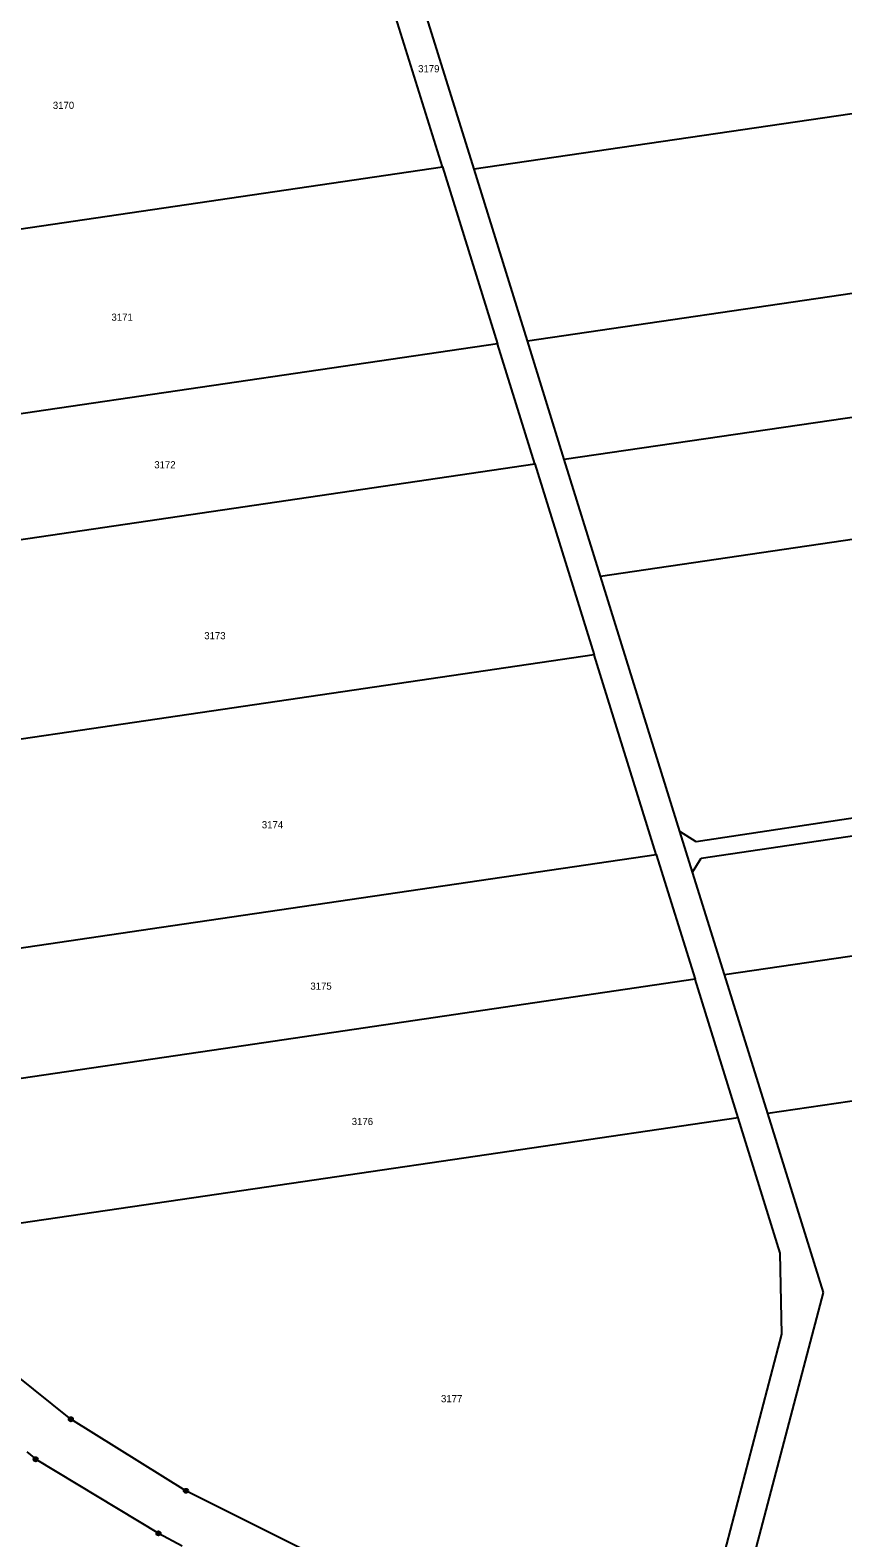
# Model space of a CAD drawing. Extents: x -618848 to -615803, y -1044450 to -1042254.
# Drawn here: x -616674.5 to -616481.6, y -1043703.1 to -1043345.1 of the extents above; entities that cross this region are included whole.
import ezdxf

# ---------------------------------------------------------------- set-up
doc = ezdxf.new("R2010")
doc.units = 0
doc.header["$LTSCALE"] = 0.68
doc.layers.add('1', color=7, linetype='Continuous', lineweight=25)
doc.layers.add('8', color=7, linetype='Continuous', lineweight=25)
doc.layers.add('2', color=7, linetype='Continuous')

msp = doc.modelspace()

# ---------------------------------------------------------------- linework, layer by layer
at = {"layer": '1'}
for p, q in [((-616576.65, -1043377.61), (-616594.71, -1043319.53)), ((-616569.16, -1043378.16), (-616585, -1043327.2)), ((-616381.88, -1043350.66), (-616569.16, -1043378.16)), ((-616682.78, -1043393.22), (-616576.65, -1043377.61)), ((-616576.65, -1043377.61), (-616563.61, -1043419.57)), ((-616556.5, -1043418.91), (-616569.16, -1043378.16)), ((-616556.5, -1043418.91), (-616369.21, -1043391.39)), ((-616547.74, -1043447.09), (-616556.5, -1043418.91)), ((-616563.61, -1043419.57), (-616673.44, -1043435.72)), ((-616554.74, -1043448.12), (-616563.61, -1043419.57)), ((-616360.43, -1043419.6), (-616547.74, -1043447.09)), ((-616673.44, -1043435.72), (-616783.28, -1043451.87)), ((-616686.08, -1043467.43), (-616554.74, -1043448.12)), ((-616554.74, -1043448.12), (-616540.64, -1043493.45)), ((-616539.15, -1043474.73), (-616547.74, -1043447.09)), ((-616539.15, -1043474.73), (-616351.87, -1043447.21)), ((-616520.29, -1043535.41), (-616539.15, -1043474.73)), ((-616540.64, -1043493.45), (-616665.34, -1043511.78)), ((-616525.91, -1043540.82), (-616540.64, -1043493.45)), ((-616665.34, -1043511.78), (-616790.05, -1043530.12)), ((-616397.75, -1043519.88), (-616516.43, -1043537.82)), ((-616515.23, -1043541.69), (-616385.24, -1043522.59)), ((-616517.31, -1043545), (-616520.29, -1043535.41)), ((-616516.43, -1043537.82), (-616520.29, -1043535.41)), ((-616643.34, -1043558.09), (-616525.91, -1043540.82)), ((-616525.91, -1043540.82), (-616516.7, -1043570.47)), ((-616517.31, -1043545), (-616515.23, -1043541.69)), ((-616509.75, -1043569.32), (-616517.31, -1043545)), ((-616509.75, -1043569.32), (-616385.23, -1043551.03)), ((-616760.77, -1043575.36), (-616643.34, -1043558.09)), ((-616499.47, -1043602.34), (-616509.75, -1043569.32)), ((-616516.7, -1043570.47), (-616628.7, -1043586.94)), ((-616506.49, -1043603.32), (-616516.7, -1043570.47)), ((-616375.69, -1043584.14), (-616499.47, -1043602.34)), ((-616628.7, -1043586.94), (-616740.7, -1043603.42)), ((-616506.49, -1043603.32), (-616609.78, -1043618.51)), ((-616496.5, -1043635.46), (-616506.49, -1043603.32)), ((-616486.26, -1043644.85), (-616499.47, -1043602.34)), ((-616609.78, -1043618.51), (-616713.07, -1043633.7)), ((-616496.08, -1043654.68), (-616496.5, -1043635.46)), ((-616506.38, -1043721.5), (-616486.26, -1043644.85)), ((-616664.83, -1043674.91), (-616693.09, -1043652.27)), ((-616513.22, -1043719.99), (-616496.08, -1043654.68)), ((-616637.53, -1043691.9), (-616664.83, -1043674.91)), ((-616675.3, -1043682.65), (-616673.17, -1043684.41)), ((-616673.17, -1043684.41), (-616644.04, -1043701.98)), ((-616602.71, -1043709.3), (-616637.53, -1043691.9)), ((-616644.04, -1043701.98), (-616638.41, -1043704.95))]:
    msp.add_line(p, q, dxfattribs=at)
at = {"layer": '8'}
for centre, radius in [((-616664.83, -1043674.9099), 0.5), ((-616664.83, -1043674.9099), 0.0303), ((-616673.17, -1043684.4099), 0.5), ((-616673.17, -1043684.4099), 0.0303), ((-616637.53, -1043691.8999), 0.5), ((-616637.53, -1043691.8999), 0.0303), ((-616644.04, -1043701.9799), 0.5), ((-616644.04, -1043701.9799), 0.0303)]:
    msp.add_circle(centre, radius, dxfattribs=at)

# ---------------------------------------------------------------- texts
at = {"layer": '2'}
for s, p in [('3179', (-616582.42, -1043355.145)), ('3170', (-616669.1, -1043363.835)), ('3171', (-616655.19, -1043414.125)), ('3172', (-616645.03, -1043449.165)), ('3173', (-616633.17, -1043489.735)), ('3174', (-616619.51, -1043534.625)), ('3175', (-616607.99, -1043572.935)), ('3176', (-616598.17, -1043605.065)), ('3177', (-616576.99, -1043670.875))]:
    msp.add_text(s, height=1.7, dxfattribs=at).set_placement(p)

doc.saveas('drawing.dxf')
